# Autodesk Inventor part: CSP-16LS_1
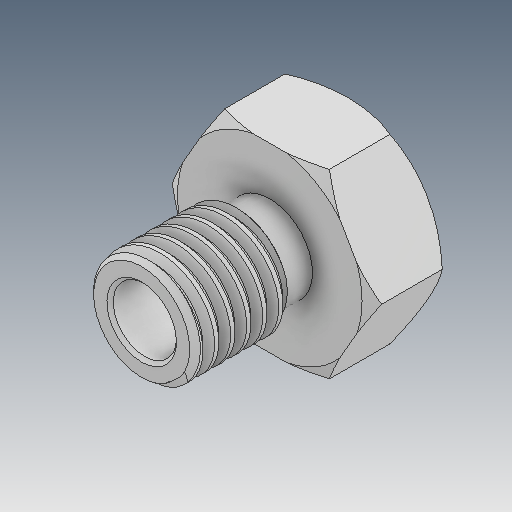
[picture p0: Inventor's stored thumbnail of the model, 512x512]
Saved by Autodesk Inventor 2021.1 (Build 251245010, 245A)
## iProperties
Created: 2021-06
Part Number: CSP-16LS_1
Material: Ogólny
Document SubType Name: Modeling
Designer: user
Density: 1 g/cm^3
Appearance: Domyślna
Author: user
Revision Number: ÈÎºÎ
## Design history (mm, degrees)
feature "ÊäÈë1"
node "Bryła1"
